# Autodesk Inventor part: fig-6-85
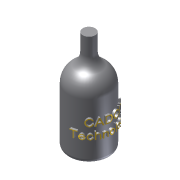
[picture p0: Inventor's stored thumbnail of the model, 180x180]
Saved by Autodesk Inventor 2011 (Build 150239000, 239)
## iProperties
Shininess: 64.0
Length Units: 11269
Angle Units: 11279
Time Units: 11290
Mass Units: 11283
Length Display Precision: 3
Angle Display Precision: 2
Compacted: True
Part Number: fig-6-85
Document SubType Name: Modeling
Created: 2002-12
Designer: deepak
Density: 1 g/cm^3
Density: 0.0
Volumn: 0.0
Area: 0.0
PropertySet Name: Model Information
Control State: 0
Master: False
Checked Out: False
Author: deepak
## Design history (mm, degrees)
node "Sketch1"
sketch "Sketch2"
  geometry: L1 (-7.653, 24.992)-(-7.653, 16.776); L2 (-14.653, 3.659)-(-14.653, -3.57); L3 (-14.653, -3.57)-(-14.653, -23.329); L4 (-14.653, -23.329)-(-4.653, -23.329); L5 (-4.653, -23.329)-(-4.653, 24.992); L6 (-4.653, 24.992)-(-7.653, 24.992); A1 r 6.757 centre (-14.41, 16.776) between (-10.649, 11.163) and (-7.653, 16.776); A2 r 9.033 centre (-5.62, 3.659) between (-10.649, 11.163) and (-14.653, 3.659)
  constraints: 12 end point, 4 point on circle, 3 tangent, 2 centre point, 2 parallel, 2 perpendicular, 1 collinear, 1 vertical
  dimensions: "d0" = 3 distance of L5.end L1.start; "d1" = 10 distance of L3.end L4.end
revolve "Revolution1" sketch "Sketch2" stored, may be unused: angle "d2" = 90 deg
fillet "Fillet1" dims "d3" = 2
workplane "Work Plane1"
workplane "Work Plane2"
sketch "Sketch3"
  geometry: L1 (-24.815, -3.793)-(24.913, -3.793); L2 (24.913, -3.793)-(24.913, -8.382); L3 (24.913, -8.382)-(-24.815, -8.382); L4 (-24.815, -8.382)-(-24.815, -3.793)
  constraints: 2 other
emboss "Emboss1" sketch "Sketch3" dims "d5" = 1, "d6" = 0
body "Solid1"
other parameters: "d4" = 3.5
